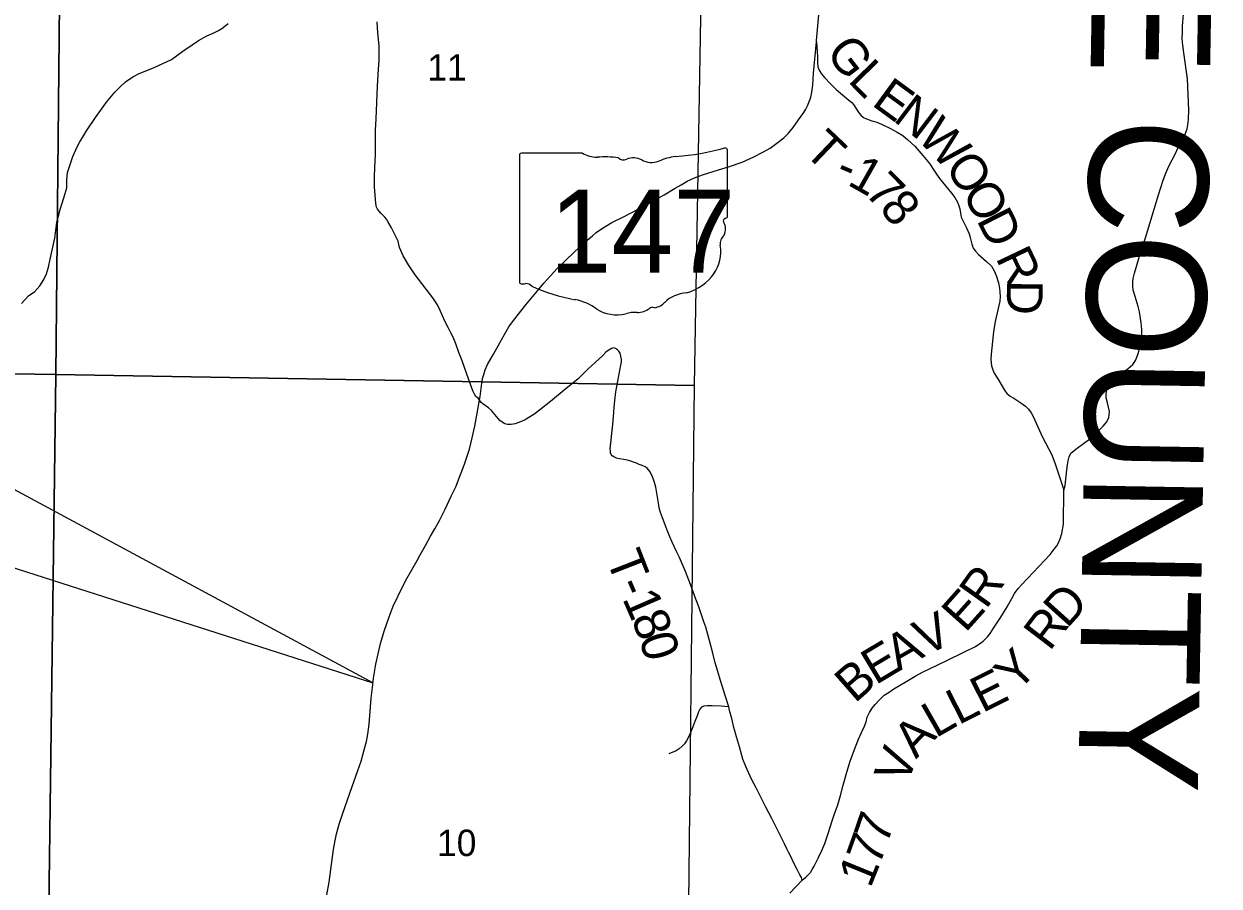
# Model space of a CAD drawing. Extents: x 0 to 34, y 0 to 22.
# Drawn here: x 5.085 to 6.979, y 16.646 to 18.013 of the extents above; entities that cross this region are included whole.
import ezdxf

# ---------------------------------------------------------------- set-up
doc = ezdxf.new("R2010")
doc.units = 0
for name, color, linetype in [('GM_X_Corporation', 7, 'Continuous'), ('GM_X_County_Text', 7, 'Continuous'), ('GM_X_Section_Text', 7, 'Continuous'), ('GM_X_State_Location', 7, 'Continuous'), ('GM_X_State_Route', 7, 'Continuous'), ('GM_X_State_Shield', 7, 'Continuous'), ('GM_X_Township_Road', 7, 'Continuous'), ('GM_X_Township_Road_Text', 7, 'Continuous'), ('SH_Text', 7, 'Continuous')]:
    doc.layers.add(name, color=color, linetype=linetype)

msp = doc.modelspace()

# ---------------------------------------------------------------- linework, layer by layer
at = {"layer": 'GM_X_Corporation'}
for points in [[(4.1319, 18.4883), (5.1454, 18.4748), (5.1353, 17.4571), (4.1176, 17.4733)], [(5.1454, 18.4748), (6.1644, 18.4533), (6.147, 17.4393), (5.1353, 17.4571)], [(4.1176, 17.4733), (5.1353, 17.4571), (5.122, 16.4496), (4.1025, 16.4586)], [(5.1353, 17.4571), (6.147, 17.4393), (6.1357, 16.427), (5.122, 16.4496)]]:
    msp.add_lwpolyline(points, close=True, dxfattribs=at)
at = {"layer": 'GM_X_State_Route'}
msp.add_lwpolyline([(5.5646, 16.6321), (5.5685, 16.6522), (5.5723, 16.68), (5.5752, 16.7039), (5.5773, 16.7153), (5.5799, 16.729), (5.5844, 16.7439), (5.5896, 16.7599), (5.6052, 16.8037), (5.6141, 16.8293), (5.6192, 16.8441), (5.6241, 16.862), (5.6275, 16.8752), (5.6299, 16.8866), (5.6321, 16.9028), (5.6353, 16.9437), (5.6372, 16.9605), (5.6387, 16.9753), (5.6423, 16.998), (5.6459, 17.0141), (5.6499, 17.0303), (5.6554, 17.0499), (5.6634, 17.0727), (5.67, 17.0899), (5.6777, 17.1061), (5.6897, 17.1299), (5.7017, 17.1511), (5.7077, 17.1621), (5.7126, 17.171), (5.721, 17.1861), (5.7289, 17.2005), (5.7358, 17.2124), (5.7433, 17.2257), (5.7524, 17.2434), (5.762, 17.2641), (5.769, 17.2791), (5.775, 17.2941), (5.7829, 17.3147), (5.7907, 17.3385), (5.795, 17.3566), (5.7993, 17.3753), (5.8065, 17.4164), (5.8075, 17.4221), (5.8102, 17.4432), (5.812, 17.4523), (5.8134, 17.4571), (5.8157, 17.4644), (5.8194, 17.4726), (5.8287, 17.4894), (5.8487, 17.5249), (5.8533, 17.5325), (5.8604, 17.5427), (5.88, 17.5673), (5.901, 17.5928), (5.9086, 17.6018), (5.93, 17.6253), (5.9565, 17.6509), (5.9644, 17.6582), (5.9747, 17.6677), (5.9857, 17.677), (5.9918, 17.682), (5.9986, 17.6871), (6.0067, 17.6921), (6.0165, 17.698), (6.0347, 17.7072), (6.0582, 17.7191), (6.0739, 17.7275), (6.0995, 17.7419), (6.1166, 17.7523), (6.1261, 17.7578), (6.136, 17.7634), (6.1473, 17.7686), (6.16, 17.7736), (6.1854, 17.7813), (6.2026, 17.7867), (6.2231, 17.7938), (6.2402, 17.8013), (6.2567, 17.8098), (6.2674, 17.816), (6.28, 17.8251), (6.2887, 17.832), (6.2964, 17.8395), (6.3039, 17.8486), (6.3124, 17.8609), (6.3206, 17.8725), (6.3237, 17.8778), (6.3263, 17.8831), (6.3297, 17.891), (6.3316, 17.8965), (6.3335, 17.9046), (6.3348, 17.9156), (6.336, 17.9347), (6.3404, 17.9842), (6.3406, 17.9867), (6.3424, 18.0038), (6.3446, 18.0271)], dxfattribs=at)
at = {"layer": 'GM_X_State_Shield'}
for p, q in [((5.8699, 17.8044), (5.8699, 17.6043)), ((5.9697, 17.8078), (5.8732, 17.8078)), ((6.1995, 17.7081), (6.1995, 17.8128)), ((6.1995, 17.7081), (6.1995, 17.7081))]:
    msp.add_line(p, q, dxfattribs=at)
for centre, major_axis, start_param, end_param in [((5.8737, 17.8048), (0.00382, 0), 1.712693, 3.28349), ((5.9927, 17.8311), (0.037, 0), 4.042523, 4.731795), ((6.0049, 17.6955), (0.133, 0), 1.404758, 1.657858), ((6.0508, 17.7827), (0.0222, 0), 0.950623, 2.079405), ((6.1267, 17.7467), (0.0703, 0), 1.699011, 2.107814), ((6.0821, 18.0807), (0.3495, 0), 4.814394, 5.042369), ((6.1958, 17.8132), (0.00367, 0), 6.141152, 7.989035), ((6.0351, 17.8059), (0.0107, 0), 3.836095, 5.185415), ((6.0795, 17.8145), (0.0267, 0), 4.081561, 5.145723), ((6.1956, 17.7077), (0.00393, 0), 5.05454, 6.418171), ((6.1986, 17.7004), (0.00568, 0), 1.883978, 3.671073), ((6.1625, 17.6872), (0.0341, 0), 5.934695, 6.695948), ((6.2126, 17.6643), (0.0248, 0), 2.387724, 3.262537), ((6.1017, 17.651), (0.0874, 0), 5.101752, 6.440018), ((5.8737, 17.6038), (0.00385, 0), 3.00124, 4.508301), ((5.8743, 17.6243), (0.0294, 0), 4.665946, 4.897461), ((5.8803, 17.5927), (0.0106, 0), 0.519207, 1.627899), ((6.0141, 17.7725), (0.2524, 0), 4.195997, 4.488961), ((5.9389, 17.5144), (0.079, 0), 0.823519, 1.323587), ((6.1385, 17.5481), (0.0479, 0), 1.647645, 2.488434), ((6.0243, 17.5917), (0.0501, 0), 4.026481, 4.996735), ((6.0533, 17.5226), (0.0412, 0), 1.495662, 1.94098), ((6.0569, 17.5768), (0.0267, 0), 4.691044, 5.507374), ((6.0811, 17.5574), (0.00752, 0), 1.147584, 2.315152), ((6.0779, 17.5849), (0.0282, 0), 4.937069, 5.64225)]:
    msp.add_ellipse(centre, major_axis=major_axis, ratio=0.8, start_param=start_param, end_param=end_param, dxfattribs=at)
at = {"layer": 'GM_X_Township_Road'}
for points in [[(6.7328, 17.2737), (6.7347, 17.2809), (6.7371, 17.3059), (6.7382, 17.314), (6.7394, 17.3202), (6.7409, 17.3266), (6.7436, 17.3323), (6.7538, 17.3402), (6.7738, 17.355), (6.7883, 17.3685), (6.7951, 17.3751), (6.8009, 17.3818), (6.8039, 17.3887), (6.8046, 17.3932), (6.8047, 17.3984), (6.8016, 17.4118), (6.7998, 17.4199), (6.7998, 17.4266), (6.8007, 17.4324), (6.8016, 17.4381), (6.8071, 17.4474), (6.8125, 17.4521), (6.8177, 17.4561), (6.8227, 17.4592), (6.8279, 17.4619), (6.8346, 17.4664), (6.8421, 17.4727), (6.8462, 17.4792), (6.8493, 17.4873), (6.8522, 17.4974), (6.8553, 17.5104), (6.856, 17.5167), (6.8563, 17.5222), (6.856, 17.5281), (6.8549, 17.5391), (6.8525, 17.5566), (6.8503, 17.5647), (6.8469, 17.5754), (6.8438, 17.586), (6.8422, 17.5909), (6.8419, 17.5968), (6.8419, 17.6032), (6.8426, 17.6092), (6.8444, 17.6179), (6.8556, 17.655), (6.862, 17.6738), (6.8824, 17.7418), (6.8899, 17.7652), (6.8944, 17.7762), (6.8989, 17.7872), (6.9096, 17.8076), (6.913, 17.8158), (6.919, 17.8271), (6.9219, 17.8319), (6.925, 17.838), (6.9278, 17.8465), (6.9292, 17.8529), (6.9302, 17.8613), (6.9307, 17.8762), (6.9285, 17.9256), (6.9228, 17.967), (6.9207, 17.9833), (6.9202, 17.9906), (6.9204, 17.9985), (6.9208, 18.009), (6.9219, 18.0283)], [(5.0811, 17.5695), (5.092, 17.5818), (5.1019, 17.5885), (5.1102, 17.5973), (5.1164, 17.6076), (5.1207, 17.6167), (5.124, 17.627), (5.1265, 17.64), (5.1336, 17.673), (5.1372, 17.6986), (5.1421, 17.7186), (5.1479, 17.737), (5.1526, 17.7529), (5.1529, 17.7655), (5.1539, 17.7771), (5.1623, 17.8028), (5.1694, 17.818), (5.1734, 17.8258), (5.1851, 17.8447), (5.1982, 17.8645), (5.2157, 17.8888), (5.2287, 17.9046), (5.2363, 17.9122), (5.2458, 17.9212), (5.2575, 17.9288), (5.2675, 17.9343), (5.2901, 17.9433), (5.3185, 17.9564), (5.3367, 17.9694), (5.3515, 17.9796), (5.3615, 17.9866), (5.3748, 17.9939), (5.3849, 17.9982), (5.3931, 18.0022), (5.3987, 18.0055), (5.4032, 18.009), (5.4084, 18.0134)], [(6.3179, 16.6553), (6.3168, 16.6593), (6.3144, 16.6639), (6.3099, 16.6724), (6.3056, 16.6801), (6.3019, 16.6881), (6.2993, 16.694), (6.2964, 16.6999), (6.2939, 16.7051), (6.29, 16.713), (6.2823, 16.729), (6.2764, 16.7406), (6.2698, 16.7533), (6.2605, 16.7711), (6.2526, 16.7869), (6.2476, 16.7964), (6.2449, 16.8017), (6.2376, 16.8153), (6.2286, 16.8355), (6.2242, 16.847), (6.2185, 16.8665), (6.2138, 16.8823), (6.2098, 16.8975), (6.2064, 16.9115), (6.203, 16.9243), (6.2016, 16.9301), (6.1964, 16.9466), (6.188, 16.9732), (6.1841, 16.9861), (6.1803, 16.9996), (6.1766, 17.0151), (6.1716, 17.0331), (6.1652, 17.0565), (6.1623, 17.0649), (6.154, 17.0885), (6.1493, 17.1007), (6.1409, 17.1239), (6.133, 17.1447), (6.1266, 17.1594), (6.1234, 17.1668), (6.1188, 17.1764), (6.1118, 17.1913), (6.1083, 17.1995), (6.104, 17.2101), (6.1009, 17.2186), (6.0965, 17.2299), (6.0935, 17.2384), (6.0916, 17.2454), (6.0902, 17.2528), (6.0878, 17.2686), (6.0859, 17.2783), (6.084, 17.2857), (6.0825, 17.2907), (6.0809, 17.2948), (6.0773, 17.3027), (6.0747, 17.3059), (6.0722, 17.3083), (6.0692, 17.3104), (6.0643, 17.3129), (6.0598, 17.3145), (6.0553, 17.3165), (6.0509, 17.3179), (6.0435, 17.3204), (6.0355, 17.3224), (6.0287, 17.3234), (6.0237, 17.3246), (6.0196, 17.3262), (6.017, 17.3278), (6.0153, 17.33), (6.0143, 17.3329), (6.0141, 17.3357), (6.014, 17.3393), (6.0178, 17.3778), (6.0193, 17.3972), (6.0199, 17.4048), (6.0209, 17.4159), (6.0228, 17.4296), (6.029, 17.4633), (6.0309, 17.4718), (6.0315, 17.4771), (6.0316, 17.481), (6.0309, 17.4861), (6.0295, 17.4907), (6.0276, 17.4939), (6.0251, 17.4963), (6.0224, 17.4982), (6.0194, 17.499), (6.0158, 17.4984), (6.0106, 17.495), (6.007, 17.4922), (6.0019, 17.4873), (5.9901, 17.4762), (5.9784, 17.4654), (5.9631, 17.4503), (5.9411, 17.4321), (5.9193, 17.4141), (5.9016, 17.4002), (5.8928, 17.3935), (5.8851, 17.3887), (5.8788, 17.3853), (5.8719, 17.3821), (5.8672, 17.3803), (5.8631, 17.3789), (5.857, 17.3779), (5.8511, 17.3778), (5.8469, 17.3788), (5.8428, 17.3812), (5.8387, 17.3843), (5.8259, 17.3997), (5.821, 17.404), (5.8122, 17.4107), (5.8093, 17.4128), (5.8065, 17.4164), (5.8056, 17.4179), (5.8045, 17.4194), (5.8008, 17.4223), (5.7986, 17.4256), (5.7965, 17.43), (5.7945, 17.4351), (5.7859, 17.459), (5.7791, 17.4785), (5.7741, 17.4917), (5.7694, 17.5055), (5.7663, 17.5134), (5.7641, 17.5181), (5.7617, 17.5222), (5.7568, 17.5314), (5.7517, 17.5418), (5.7443, 17.5587), (5.7401, 17.5675), (5.733, 17.5786), (5.7047, 17.6151), (5.6942, 17.6311), (5.6859, 17.6451), (5.6801, 17.6584), (5.6776, 17.6684), (5.6718, 17.68), (5.6673, 17.6894), (5.6617, 17.6997), (5.6596, 17.7033), (5.6569, 17.7065), (5.6511, 17.7121), (5.6451, 17.719), (5.6437, 17.7224), (5.6423, 17.728), (5.6402, 17.7543), (5.6401, 17.7704), (5.6409, 17.7852), (5.6417, 17.8057), (5.6417, 17.8253), (5.642, 17.8441), (5.6428, 17.8623), (5.645, 17.9141), (5.6469, 17.941), (5.6475, 17.9552), (5.6479, 17.9658), (5.6478, 17.9783), (5.6457, 17.9985), (5.6446, 18.0161)], [(6.3404, 17.9842), (6.3419, 17.969), (6.3421, 17.9608), (6.3421, 17.9515), (6.343, 17.9447), (6.3448, 17.9395), (6.3478, 17.934), (6.3532, 17.928), (6.3626, 17.9177), (6.372, 17.909), (6.3919, 17.8921), (6.3965, 17.8882), (6.3994, 17.8848), (6.4079, 17.872), (6.4108, 17.8682), (6.415, 17.8647), (6.4201, 17.8623), (6.4281, 17.8594), (6.4363, 17.8569), (6.4439, 17.8538), (6.4569, 17.8474), (6.4685, 17.8412), (6.4773, 17.8357), (6.4856, 17.8291), (6.4964, 17.8188), (6.5092, 17.8042), (6.5195, 17.7915), (6.5287, 17.7779), (6.5354, 17.7677), (6.5544, 17.7447), (6.5598, 17.7374), (6.564, 17.7302), (6.5659, 17.7261), (6.5677, 17.7195), (6.569, 17.7128), (6.5698, 17.7063), (6.5782, 17.6894), (6.5826, 17.6798), (6.5843, 17.674), (6.5868, 17.6634), (6.5891, 17.6573), (6.5924, 17.6527), (6.5976, 17.647), (6.6102, 17.6362), (6.6181, 17.6287), (6.6221, 17.6216), (6.6255, 17.6139), (6.6288, 17.6023), (6.6306, 17.594), (6.6314, 17.5876), (6.6316, 17.5805), (6.6311, 17.573), (6.6239, 17.5408), (6.6212, 17.5244), (6.6174, 17.4892), (6.617, 17.4811), (6.6172, 17.4755), (6.618, 17.4705), (6.6202, 17.4642), (6.6223, 17.4593), (6.6279, 17.4499), (6.6388, 17.4321), (6.6424, 17.4266), (6.6473, 17.4225), (6.6532, 17.4192), (6.6645, 17.4123), (6.6719, 17.4069), (6.6767, 17.4018), (6.6807, 17.396), (6.6838, 17.3902), (6.699, 17.3576), (6.7134, 17.3296), (6.7187, 17.3156), (6.7282, 17.287), (6.7328, 17.2737)], [(6.2983, 16.6347), (6.3179, 16.6553), (6.3235, 16.6599), (6.3271, 16.6632), (6.3309, 16.6677), (6.3339, 16.6724), (6.3369, 16.6776), (6.3433, 16.69), (6.3491, 16.7024), (6.3539, 16.7135), (6.3591, 16.7294), (6.3656, 16.7492), (6.3692, 16.7604), (6.3744, 16.7748), (6.3787, 16.7896), (6.3827, 16.8059), (6.3888, 16.8266), (6.3942, 16.8442), (6.4024, 16.8669), (6.4072, 16.8788), (6.4119, 16.8894), (6.4168, 16.8993), (6.4191, 16.9064), (6.421, 16.9136), (6.4228, 16.9177), (6.4244, 16.9211), (6.4287, 16.928), (6.4334, 16.9338), (6.4398, 16.9407), (6.4481, 16.9484), (6.4557, 16.9536), (6.463, 16.9585), (6.4814, 16.9692), (6.4971, 16.9787), (6.5099, 16.9857), (6.5207, 16.9911), (6.5462, 17.0032), (6.5753, 17.0175), (6.5924, 17.026), (6.6012, 17.0316), (6.605, 17.0344), (6.6081, 17.0372), (6.6117, 17.0411), (6.6156, 17.0463), (6.6211, 17.0548), (6.6325, 17.072), (6.643, 17.0884), (6.6499, 17.1021), (6.6544, 17.11), (6.66, 17.1177), (6.666, 17.1243), (6.7107, 17.1718), (6.7174, 17.1799), (6.7215, 17.1855), (6.7243, 17.1903), (6.727, 17.1966), (6.7293, 17.2049), (6.732, 17.2198), (6.7328, 17.2737)], [(6.2016, 16.9301), (6.1947, 16.9308), (6.1895, 16.9309), (6.1752, 16.9316), (6.1676, 16.9317), (6.1624, 16.931), (6.1582, 16.9293), (6.1558, 16.9265), (6.1539, 16.9224), (6.1515, 16.9158), (6.1481, 16.9071), (6.1432, 16.8939), (6.1383, 16.8828), (6.1346, 16.8763), (6.1313, 16.8713), (6.1277, 16.8675), (6.1233, 16.8636), (6.1183, 16.8605), (6.1066, 16.8558)]]:
    msp.add_lwpolyline(points, dxfattribs=at)
at = {"layer": 'SH_Text'}
msp.add_lwpolyline([(5.6379, 16.9679), (4.5397, 17.56), (4.5397, 17.32)], close=True, dxfattribs=at)

# ---------------------------------------------------------------- texts
at = {"layer": 'GM_X_County_Text'}
msp.add_text('NOBLE COUNTY', height=0.189394, rotation=269.0214, dxfattribs=at).set_placement((6.7895, 18.7934))
at = {"layer": 'GM_X_Section_Text'}
for s, p in [('11', (5.7241, 17.9229)), ('10', (5.7395, 16.6935))]:
    msp.add_text(s, height=0.04186, rotation=0, dxfattribs=at).set_placement(p)
at = {"layer": 'GM_X_State_Location'}
for s in ['s', 'r']:
    msp.add_text(s, height=0.000189, dxfattribs=at).set_placement((6.031, 17.691))
msp.add_text('147', height=0.000189, rotation=0, dxfattribs=at).set_placement((5.9641, 17.6773))
at = {"layer": 'GM_X_State_Shield'}
msp.add_text('147', height=0.13184, dxfattribs=at).set_placement((5.9178, 17.6184))
at = {"layer": 'GM_X_Township_Road_Text'}
for s, rotation, p in [('G', 307.6932, (6.3537, 17.9671)), ('L', 314.28, (6.3889, 17.9221)), ('E', 323.8527, (6.4264, 17.8849)), ('N', 322.8161, (6.4605, 17.86)), ('W', 313.3076, (6.4985, 17.8314)), ('T', 316.3759, (6.3188, 17.8087)), ('O', 305.4928, (6.5424, 17.7851)), ('-', 336.703, (6.3678, 17.7673)), ('1', 330.5152, (6.3878, 17.7588)), ('7', 314.448, (6.415, 17.7441)), ('8', 309.5717, (6.4386, 17.7201)), ('O', 297.7854, (6.5704, 17.7461)), ('D', 296.8502, (6.5935, 17.7021)), ('R', 295.4654, (6.6239, 17.6422)), ('D', 269.3224, (6.6425, 17.6067)), ('T', 291.3581, (6.0067, 17.1652)), ('R', 54.6032, (6.6093, 17.0835)), ('-', 293.4444, (6.023, 17.1236)), ('D', 48.0331, (6.7376, 17.0531)), ('1', 293.5899, (6.0324, 17.102)), ('E', 48.2074, (6.5766, 17.0464)), ('8', 292.3397, (6.0462, 17.0702)), ('V', 26.236, (6.513, 17.01)), ('R', 52.6508, (6.71, 17.017)), ('0', 286.2985, (6.059, 17.0394)), ('A', 29.781, (6.4704, 16.9856)), ('E', 30.9101, (6.4342, 16.9639)), ('Y', 46.3957, (6.6586, 16.9516)), ('B', 41.2439, (6.4013, 16.9347)), ('E', 26.6455, (6.6035, 16.9198)), ('L', 26.8046, (6.5656, 16.9007)), ('L', 29.8826, (6.5295, 16.8799)), ('A', 46.2726, (6.4983, 16.8464)), ('V', 69.5753, (6.484, 16.8047)), ('7', 71.0166, (6.4521, 16.71)), ('7', 70.3643, (6.4401, 16.6764)), ('1', 67.823, (6.4259, 16.6414))]:
    msp.add_text(s, height=0.0568, rotation=rotation, dxfattribs=at).set_placement(p)

doc.saveas('drawing.dxf')
